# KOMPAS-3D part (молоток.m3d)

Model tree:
1. Смещенная плоскость:1
     Расстояние = 14
2. Смещенная плоскость:2
     Расстояние = 14
3. Смещенная плоскость:3
     Расстояние = 5
4. Смещенная плоскость:4
     Расстояние = 20
5. Смещенная плоскость:5
     Расстояние = 5
6. Смещенная плоскость:6
     Расстояние = 16
7. Смещенная плоскость:7
     Расстояние = 2.5
8. Эскиз:1
9. Эскиз:2
10. Эскиз:3
11. Эскиз:4
12. Эскиз:5
13. Эскиз:6
14. Эскиз:7
15. Эскиз:8
16. Операция по сечениям:1
     Толщина стенки 1 = 1; Толщина стенки 2 = 1
17. Операция по сечениям:2
     Толщина стенки 1 = 1; Толщина стенки 2 = 1
18. Операция по сечениям:3
     Толщина стенки 1 = 1; Толщина стенки 2 = 1
19. Операция по сечениям:4
     Толщина стенки 1 = 1; Толщина стенки 2 = 1
20. Операция по сечениям:5
     Толщина стенки 1 = 1; Толщина стенки 2 = 1
21. Скругление:1
     Радиус = 0.5
22. Скругление:2
     Радиус = 0.2
23. Скругление:3
     Радиус = 1
24. Скругление:4
     Радиус = 1
25. Скругление:5
     Радиус = 1
26. Скругление:6
     Радиус = 1
27. Скругление:7
     Радиус = 0.5
28. Скругление:8
     Радиус = 0.5
29. Скругление:9
     Радиус = 0.5
30. Скругление:10
     Радиус = 0.5
31. Скругление:11
     Радиус = 0.5
32. Скругление:12
     Радиус = 0.5
33. Эскиз:9
34. Вырезать элемент выдавливания:1
     Расстояние 2 = 12.6148; Угол 2 = 2; Расстояние 1 = 12.6148; Угол 1 = 2
35. Скругление:13
     Радиус = 1
36. Скругление:14
     Радиус = 1
37. Скругление:15
     Радиус = 1
38. Скругление:16
     Радиус = 1
